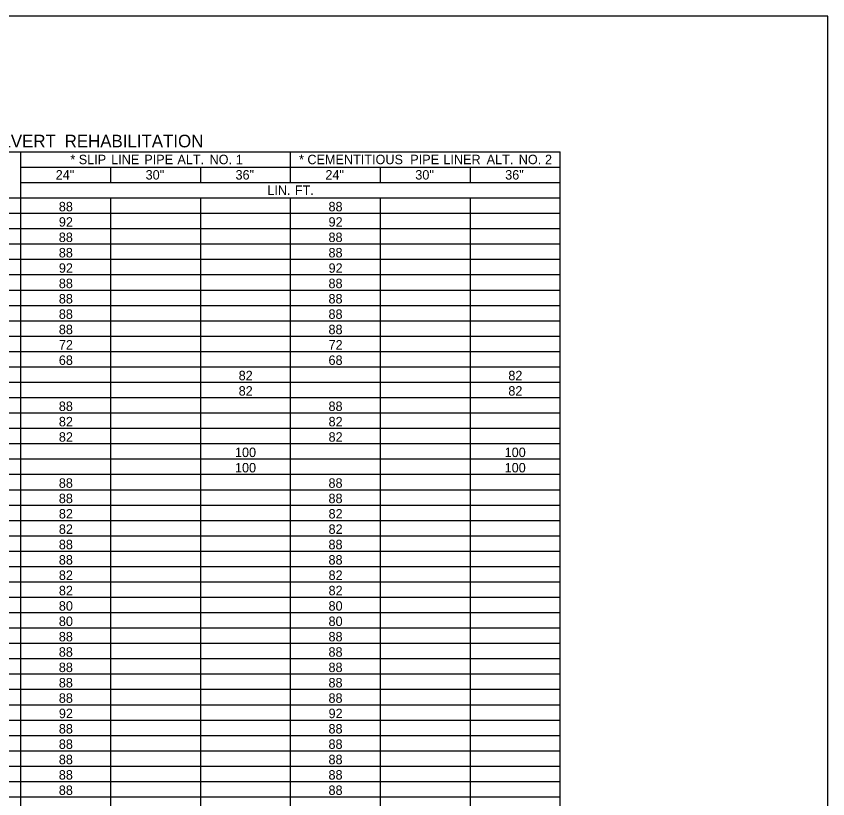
# Model space of a CAD drawing. Extents: x 2261867 to 2275370, y -3124789 to -3122260.
# Drawn here: x 2265400 to 2265915, y -3124272 to -3123775 of the extents above; entities that cross this region are included whole.
import ezdxf

# ---------------------------------------------------------------- set-up
doc = ezdxf.new("R2010")
doc.units = 0
doc.layers.add('DSN_DRFT_Named-Boundary', color=7, linetype='Continuous')
doc.layers.add('DSN_QNTY_Annotation', color=7, linetype='Continuous')

msp = doc.modelspace()

# ---------------------------------------------------------------- linework, layer by layer
at = {"layer": 'DSN_DRFT_Named-Boundary'}
msp.add_lwpolyline([(2264290.05, -3124774.39), (2265915.05, -3124774.39), (2265915.05, -3123775.33), (2264290.05, -3123775.33)], close=True, dxfattribs=at)
at = {"layer": 'DSN_QNTY_Annotation'}
for p, q in [((2265154.48, -3123861.39), (2265745.33, -3123861.39)), ((2265403.1, -3124516.11), (2265403.1, -3123861.39)), ((2265574.22, -3123880.89), (2265574.22, -3123861.39)), ((2265574.22, -3123871.14), (2265574.22, -3123861.39)), ((2265745.33, -3124516.11), (2265745.33, -3123861.39)), ((2265745.33, -3124516.11), (2265745.33, -3123861.39)), ((2265403.1, -3123871.14), (2265745.33, -3123871.14)), ((2265460.14, -3123880.89), (2265460.14, -3123871.14)), ((2265517.18, -3123880.89), (2265517.18, -3123871.14)), ((2265631.25, -3123880.89), (2265631.25, -3123871.14)), ((2265688.29, -3123880.89), (2265688.29, -3123871.14)), ((2265403.1, -3123880.89), (2265745.33, -3123880.89)), ((2265403.1, -3124516.11), (2265403.1, -3123880.89)), ((2265154.48, -3123890.64), (2265745.33, -3123890.64)), ((2265460.14, -3124505.38), (2265460.14, -3123890.64)), ((2265460.14, -3124516.11), (2265460.14, -3123890.64)), ((2265517.18, -3124505.38), (2265517.18, -3123890.64)), ((2265517.18, -3124516.11), (2265517.18, -3123890.64)), ((2265574.22, -3124516.11), (2265574.22, -3123890.64)), ((2265631.25, -3124505.38), (2265631.25, -3123890.64)), ((2265631.25, -3124516.11), (2265631.25, -3123890.64)), ((2265688.29, -3124505.38), (2265688.29, -3123890.64)), ((2265688.29, -3124516.11), (2265688.29, -3123890.64)), ((2265154.48, -3123900.39), (2265745.33, -3123900.39)), ((2265154.48, -3123910.14), (2265745.33, -3123910.14)), ((2265154.48, -3123919.89), (2265745.33, -3123919.89)), ((2265154.48, -3123929.64), (2265745.33, -3123929.64)), ((2265154.48, -3123939.39), (2265745.33, -3123939.39)), ((2265154.48, -3123949.14), (2265745.33, -3123949.14)), ((2265154.48, -3123958.89), (2265745.33, -3123958.89)), ((2265154.48, -3123968.64), (2265745.33, -3123968.64)), ((2265154.48, -3123978.39), (2265745.33, -3123978.39)), ((2265154.48, -3123988.14), (2265745.33, -3123988.14)), ((2265154.48, -3123997.89), (2265745.33, -3123997.89)), ((2265154.48, -3124007.64), (2265745.33, -3124007.64)), ((2265154.48, -3124017.39), (2265745.33, -3124017.39)), ((2265154.48, -3124027.14), (2265745.33, -3124027.14)), ((2265154.48, -3124036.89), (2265745.33, -3124036.89)), ((2265154.48, -3124046.64), (2265745.33, -3124046.64)), ((2265154.48, -3124056.39), (2265745.33, -3124056.39)), ((2265154.48, -3124066.14), (2265745.33, -3124066.14)), ((2265154.48, -3124075.89), (2265745.33, -3124075.89)), ((2265154.48, -3124085.64), (2265745.33, -3124085.64)), ((2265154.48, -3124095.39), (2265745.33, -3124095.39)), ((2265154.48, -3124105.14), (2265745.33, -3124105.14)), ((2265154.48, -3124114.89), (2265745.33, -3124114.89)), ((2265154.48, -3124124.64), (2265745.33, -3124124.64)), ((2265154.48, -3124134.39), (2265745.33, -3124134.39)), ((2265154.48, -3124144.14), (2265745.33, -3124144.14)), ((2265154.48, -3124153.89), (2265745.33, -3124153.89)), ((2265154.48, -3124163.64), (2265745.33, -3124163.64)), ((2265154.48, -3124173.39), (2265745.33, -3124173.39)), ((2265154.48, -3124183.14), (2265745.33, -3124183.14)), ((2265154.48, -3124192.89), (2265745.33, -3124192.89)), ((2265154.48, -3124202.64), (2265745.33, -3124202.64)), ((2265154.48, -3124212.39), (2265745.33, -3124212.39)), ((2265154.48, -3124222.14), (2265745.33, -3124222.14)), ((2265154.48, -3124231.89), (2265745.33, -3124231.89)), ((2265154.48, -3124241.64), (2265745.33, -3124241.64)), ((2265154.48, -3124251.39), (2265745.33, -3124251.39)), ((2265154.48, -3124261.14), (2265745.33, -3124261.14)), ((2265154.48, -3124270.89), (2265745.33, -3124270.89))]:
    msp.add_line(p, q, dxfattribs=at)

# ---------------------------------------------------------------- texts
for s, height, p in [('CULVERT', 8, (2265375.32, -3123858.57)), (' REHABILITATION', 8, (2265427.89, -3123858.57)), ('*', 6, (2265434.48, -3123869.27)), (' SLIP', 6, (2265437.57, -3123869.27)), (' LINE', 6, (2265458.15, -3123869.27)), (' PIPE', 6, (2265479.15, -3123869.27)), (' ALT.', 6, (2265500.17, -3123869.27)), (' NO.', 6, (2265520.55, -3123869.27)), (' 1', 6, (2265537.21, -3123869.27)), ('*', 6, (2265579.57, -3123869.27)), (' CEMENTITIOUS', 6, (2265582.65, -3123869.27)), (' PIPE', 6, (2265647.92, -3123869.27)), (' LINER', 6, (2265668.93, -3123869.27)), (' ALT.', 6, (2265696.37, -3123869.27)), (' NO.', 6, (2265716.75, -3123869.27)), (' 2', 6, (2265733.41, -3123869.27)), ('24"', 6, (2265425.18, -3123879.02)), ('30"', 6, (2265482.22, -3123879.02)), ('36"', 6, (2265539.26, -3123879.02)), ('24"', 6, (2265596.3, -3123879.02)), ('30"', 6, (2265653.33, -3123879.02)), ('36"', 6, (2265710.37, -3123879.02)), ('LIN.', 6, (2265559.43, -3123888.77)), (' FT.', 6, (2265574.68, -3123888.77)), ('88', 6, (2265427.15, -3123899.19)), ('88', 6, (2265598.26, -3123899.19)), ('92', 6, (2265427.18, -3123908.94)), ('92', 6, (2265598.3, -3123908.94)), ('88', 6, (2265427.15, -3123918.69)), ('88', 6, (2265598.26, -3123918.69)), ('88', 6, (2265427.15, -3123928.44)), ('88', 6, (2265598.26, -3123928.44)), ('92', 6, (2265427.18, -3123938.19)), ('92', 6, (2265598.3, -3123938.19)), ('88', 6, (2265427.15, -3123947.94)), ('88', 6, (2265598.26, -3123947.94)), ('88', 6, (2265427.15, -3123957.69)), ('88', 6, (2265598.26, -3123957.69)), ('88', 6, (2265427.15, -3123967.44)), ('88', 6, (2265598.26, -3123967.44)), ('88', 6, (2265427.15, -3123977.19)), ('88', 6, (2265598.26, -3123977.19)), ('72', 6, (2265427.18, -3123986.94)), ('72', 6, (2265598.3, -3123986.94)), ('68', 6, (2265427.15, -3123996.69)), ('68', 6, (2265598.26, -3123996.69)), ('82', 6, (2265541.26, -3124006.44)), ('82', 6, (2265712.37, -3124006.44)), ('82', 6, (2265541.26, -3124016.19)), ('82', 6, (2265712.37, -3124016.19)), ('88', 6, (2265427.15, -3124025.94)), ('88', 6, (2265598.26, -3124025.94)), ('82', 6, (2265427.18, -3124035.69)), ('82', 6, (2265598.3, -3124035.69)), ('82', 6, (2265427.18, -3124045.44)), ('82', 6, (2265598.3, -3124045.44)), ('100', 6, (2265538.91, -3124055.19)), ('100', 6, (2265710.02, -3124055.19)), ('100', 6, (2265538.91, -3124064.94)), ('100', 6, (2265710.02, -3124064.94)), ('88', 6, (2265427.15, -3124074.69)), ('88', 6, (2265598.26, -3124074.69)), ('88', 6, (2265427.15, -3124084.44)), ('88', 6, (2265598.26, -3124084.44)), ('82', 6, (2265427.18, -3124094.19)), ('82', 6, (2265598.3, -3124094.19)), ('82', 6, (2265427.18, -3124103.94)), ('82', 6, (2265598.3, -3124103.94)), ('88', 6, (2265427.15, -3124113.69)), ('88', 6, (2265598.26, -3124113.69)), ('88', 6, (2265427.15, -3124123.44)), ('88', 6, (2265598.26, -3124123.44)), ('82', 6, (2265427.18, -3124133.19)), ('82', 6, (2265598.3, -3124133.19)), ('82', 6, (2265427.18, -3124142.94)), ('82', 6, (2265598.3, -3124142.94)), ('80', 6, (2265427.16, -3124152.69)), ('80', 6, (2265598.28, -3124152.69)), ('80', 6, (2265427.16, -3124162.44)), ('80', 6, (2265598.28, -3124162.44)), ('88', 6, (2265427.15, -3124172.19)), ('88', 6, (2265598.26, -3124172.19)), ('88', 6, (2265427.15, -3124181.94)), ('88', 6, (2265598.26, -3124181.94)), ('88', 6, (2265427.15, -3124191.69)), ('88', 6, (2265598.26, -3124191.69)), ('88', 6, (2265427.15, -3124201.44)), ('88', 6, (2265598.26, -3124201.44)), ('88', 6, (2265427.15, -3124211.19)), ('88', 6, (2265598.26, -3124211.19)), ('92', 6, (2265427.18, -3124220.94)), ('92', 6, (2265598.3, -3124220.94)), ('88', 6, (2265427.15, -3124230.69)), ('88', 6, (2265598.26, -3124230.69)), ('88', 6, (2265427.15, -3124240.44)), ('88', 6, (2265598.26, -3124240.44)), ('88', 6, (2265427.15, -3124250.19)), ('88', 6, (2265598.26, -3124250.19)), ('88', 6, (2265427.15, -3124259.94)), ('88', 6, (2265598.26, -3124259.94)), ('88', 6, (2265427.15, -3124269.69)), ('88', 6, (2265598.26, -3124269.69))]:
    msp.add_text(s, height=height, dxfattribs=at).set_placement(p)

doc.saveas('drawing.dxf')
